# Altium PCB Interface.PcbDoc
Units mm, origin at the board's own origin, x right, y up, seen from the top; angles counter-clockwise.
Board outline 30.5 x 82 mm, 2 copper layers (Top Layer, Bottom Layer), stack 1.271 mm thick; 75 components, 43 nets, 233 pads, 361 vias.
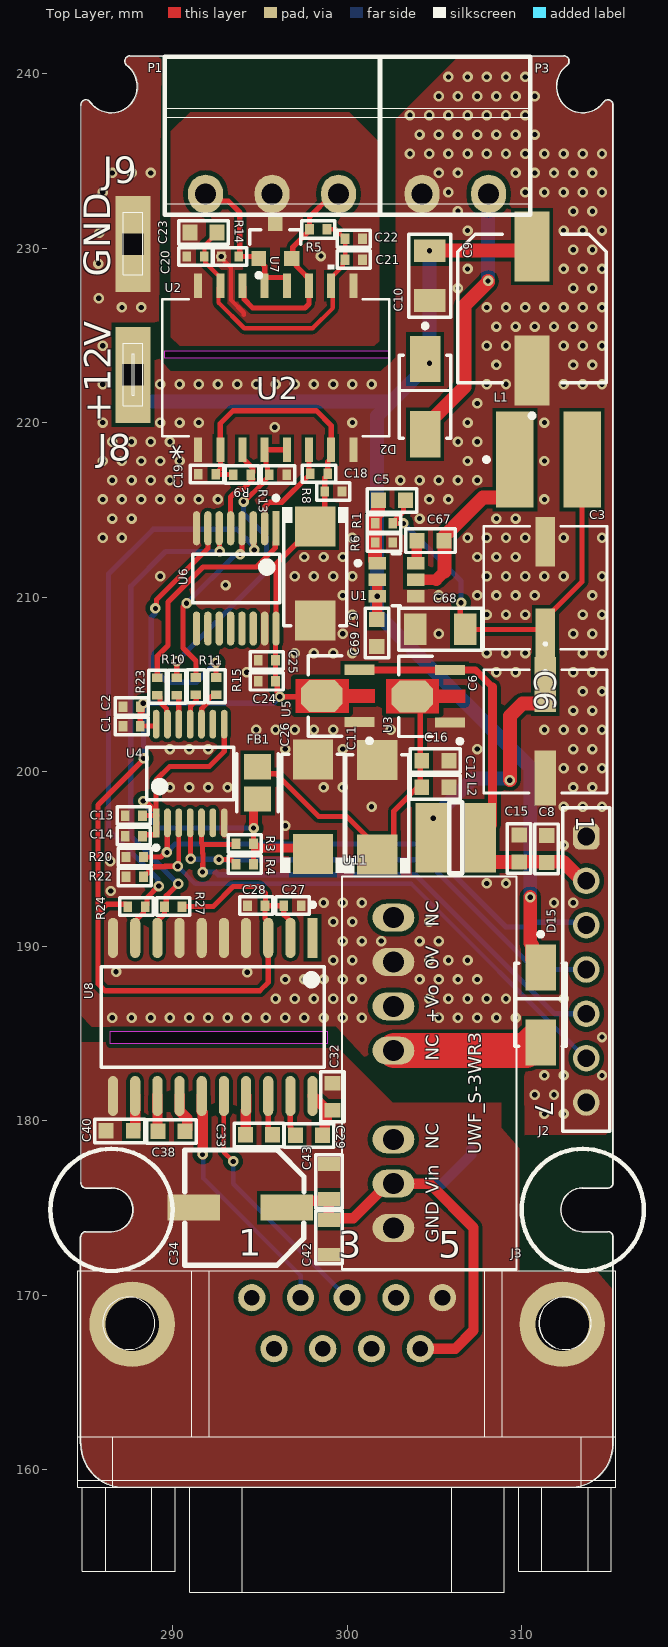
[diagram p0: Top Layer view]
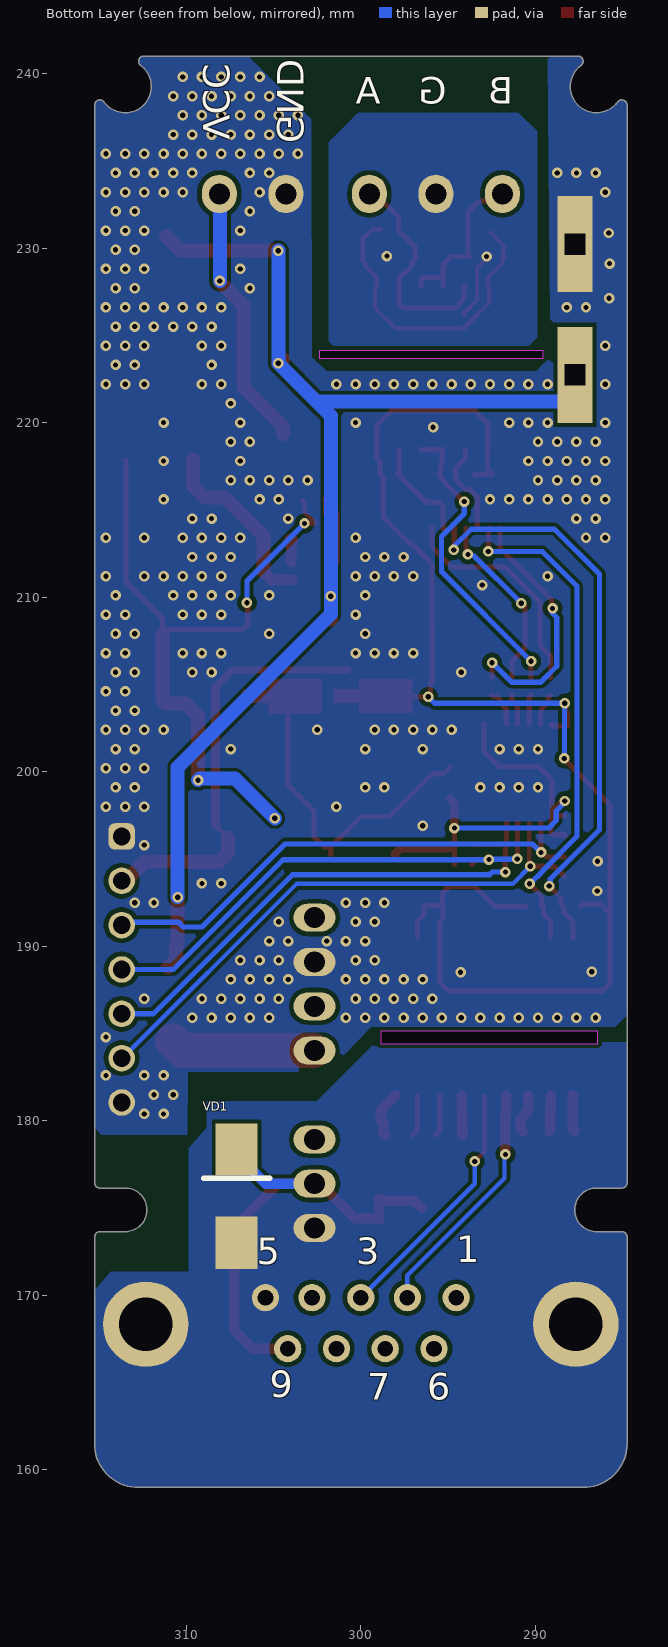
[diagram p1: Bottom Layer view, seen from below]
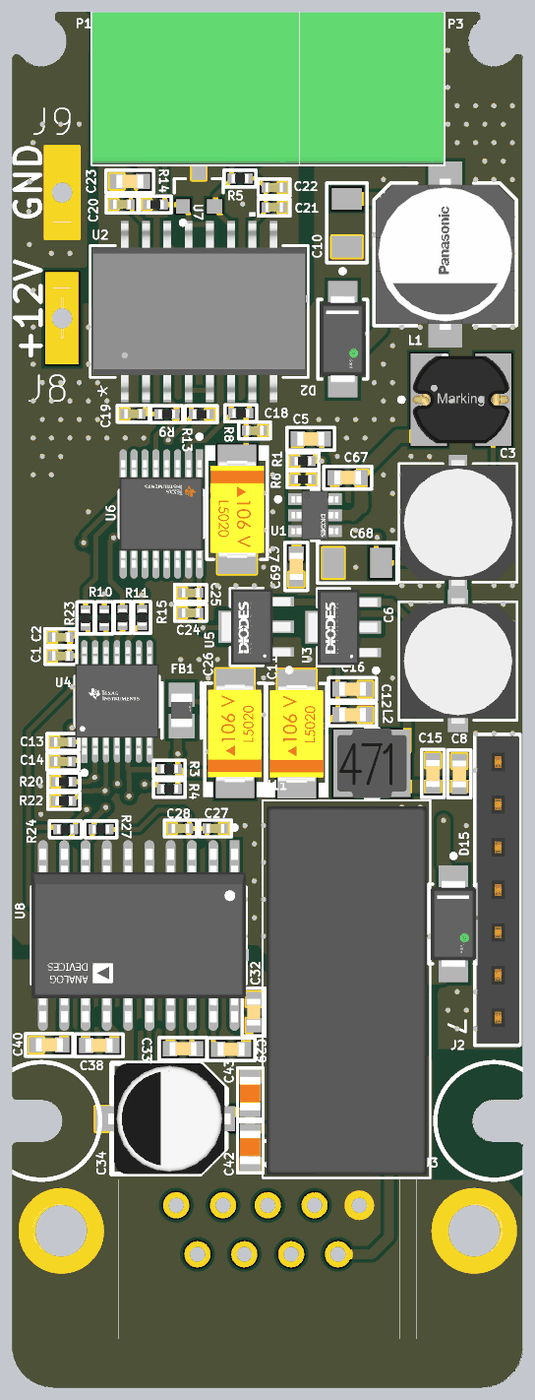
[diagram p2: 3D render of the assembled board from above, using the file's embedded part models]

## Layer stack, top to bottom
Top Solder: solder mask 0.0102, Solder Resist, Dk 3.5
Top Layer: signal copper 0.0356
Dielectric 1: dielectric 1.2, FR-4, Dk 4.8
Bottom Layer: signal copper 0.0356
Bottom Solder: solder mask 0.0102, Solder Resist, Dk 3.5

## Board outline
284.75,173.35 cw(c285.05,173.35) 285.05,173.65 286.5,173.65 ccw(c286.5,174.9) 286.5,176.15 285.05,176.15 cw(c285.05,176.45) 284.75,176.45 284.75,238.183 cw(c285.05,238.183) 285.292,238.361 ccw(c286.5,239.25) 287.389,240.458 cw(c287.567,240.7) 287.567,241 312.433,241 cw(c312.433,240.7) 312.611,240.458 ccw(c313.5,239.25) 314.708,238.361 cw(c314.95,238.183) 315.25,238.183 315.25,176.45 cw(c314.95,176.45) 314.95,176.15 313.5,176.15 ccw(c313.5,174.9) 313.5,173.65 314.95,173.65 cw(c314.95,173.35) 315.25,173.35 315.25,161.5 cw(c312.75,161.5) 312.75,159 287.25,159 cw(c287.25,161.5) 284.75,161.5
cut-out: 289.56,223.672 289.56,224.13 302.387,224.13 302.387,223.672
cut-out: 286.436,184.429 286.436,185.141 298.856,185.141 298.856,184.429
cut-out: 289.56,223.672 289.56,224.13 302.387,224.13 302.387,223.672

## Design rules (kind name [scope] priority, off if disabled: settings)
Clearance Clearance_1 [All] p1: gap=0.254 ignorepadtopadclearanceinfootprint=FALSE except(0.2: Arc-Fill Arc-Poly Arc-Region Track-Fill Track-Poly Track-Region SMDPad-SMDPad SMDPad-THPad SMDPad-Fill SMDPad-Poly SMDPad-Region)
Clearance [All] p2: gap=0.254 ignorepadtopadclearanceinfootprint=TRUE except(0.15: Via-Fill Via-Poly Via-Region; 0.2: Arc-Fill Arc-Poly Arc-Region Track-Fill Track-Poly Track-Region SMDPad-SMDPad SMDPad-Fill SMDPad-Poly SMDPad-Region)
ComponentClearance [All] p1: gap=-10 collisioncheckmode=3 verticalgap=0.1 showdistances=FALSE
HoleSize [All] p1: absolutevalues=TRUE maxlimit=4 minlimit=0.025 maxpercent=80.000 minpercent=20.000
PlaneClearance [All] p1: clearance=0.2
PlaneConnect [All] p1: planeconnectstyle=Direct reliefexpansion=0.508 reliefentries=4 reliefconductorwidth=0.254 reliefairgap=0.254
PolygonConnect [All] p1: connectstyle=Direct reliefconductorwidth=0.254 reliefentries=4 polygonreliefangle="90 Angle" airgapwidth=0.254
RoutingVias [All] p1: holewidth=0.3 width=0.6 viastyle="Through Hole" minholewidth=0.3 minwidth=0.6 maxholewidth=0.711 maxwidth=1.27
SilkToSilkClearance [All] p1: silktosilkclearance=0.1
SilkToSolderMaskClearance [IsPad] p1: minsilkscreentomaskgap=0.05 clearancetoexposedcopper=TRUE
SolderMaskExpansion SolderMaskExpansion_1 [All] p1: expansion=0.102 istentingtop=FALSE
SolderMaskExpansion Tented_Vias [IsVia] p2: expansion=0.102 istentingtop=TRUE
SupplyNets "Schematic Supply Nets_10" [InNet('VCC_2')] p1: voltage=0.000
SupplyNets "Schematic Supply Nets_8" [InNet('GND_ISOL')] p2: voltage=0.000
SupplyNets "Schematic Supply Nets_5" [InNet('3v3')] p3: voltage=0.000
SupplyNets "Schematic Supply Nets_4" [InNet('VCC')] p4: voltage=0.000
SupplyNets "Schematic Supply Nets_2" [InNet('+5V')] p5: voltage=0.000
SupplyNets "Schematic Supply Nets_1" [InNet('GND')] p6: voltage=0.000
SupplyNets "Schematic Supply Nets" [InNet('GND_2')] p7: voltage=0.000
Width [All] p1: maxlimit=3 minlimit=0.254 preferedwidth=0.254 minimp=50.000000 maximp=50.000000 favimp=50.000000
24 further rules are at their usual default settings.

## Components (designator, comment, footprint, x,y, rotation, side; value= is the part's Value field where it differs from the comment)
C1 "0.1uF 16V" CAP-0402 287.655,202.616 r180 top locked
C2 "2.2uF 16V" CAP-0402 287.655,203.733 r180 top locked
C3 "100uF 16V" CAP_A765EB_KEM-L 311.353,210.541 r90 top locked
C5 "100pF" CAP-0603 302.565,215.544 r180 top locked
C6 "100uF 16V" CAP_A765EB_KEM 311.353,202.311 r270 top locked
C7 "100uF_16V" CAP-TAN-C 298.171,211.353 r270 top locked
C8 "0.1uF" CAP-0603 311.429,195.58 r270 top locked
C9 "330uF 25V" CAP_SMD_Size_G 310.591,226.543 r90 top locked
C10 "10uF 50V" CAP-1206 304.724,228.422 r270 top locked
C11 "47uF_16V" CAP-TAN-C 301.727,197.968 r90 top locked
C12 "0.1uF" CAP-0603 305.054,199.111 r180 top locked
C13 "0.1uF 16V" CAP-0402 287.782,197.485 r180 top locked
C14 "2.2uF 16V" CAP-0402 287.782,196.317 r180 top locked
C15 "0.1uF" CAP-0603 309.855,195.605 r270 top locked
C16 "0.1uF" CAP-0603 305.054,200.635 r180 top locked
C18 "2.2uF 16V" CAP-0402 299.212,216.052 r0 top locked
C19 "0.1uF 16V" CAP-0402 291.973,217.043 r180 top locked
C20 "10nF" CAP-0402 291.313,229.514 r180 top locked
C21 "100nF" CAP-0402 300.38,229.337 r0 top locked
C22 "1nF" CAP-0402 300.38,230.53 r0 top locked
C23 "1uF" CAP-0603 291.77,230.886 r180 top locked
C24 "2.2uF 16V" CAP-0402 295.402,205.181 r180 top locked
C25 "0.1uF 16V" CAP-0402 295.402,206.375 r180 top locked
C26 "100uF_16V" CAP-TAN-C 298.044,197.993 r90 top locked
C27 "2.2uF 16V" CAP-0402 296.875,192.329 r0 top locked
C28 "0.1uF 16V" CAP-0402 294.792,192.329 r180 top locked
C29 "0.1uF 16V" CAP-0603 297.815,179.172 r0 top locked
C32 "0.1uF 16V" CAP-0603 299.161,181.381 r270 top locked
C33 "0.1uF 16V" CAP-0603 294.945,179.197 r0 top locked
C34 "100uF 50V" CAP_SMD_SIZE_D 294.132,175.031 r0 top locked
C38 "0.1uF 16V" CAP-0603 289.941,179.4 r0 top locked
C40 "0.1uF 16V" CAP-0603 286.969,179.426 r0 top locked
C42 "1 uF 25V" CAP-0805 298.958,173.33 r270 top locked
C43 "100 nF 25V" CAP-0805 298.958,176.53 r90 top locked
C67 "100nF" CAP-0603 304.775,213.233 r0 top locked
C68 "22uF 16V" CAP-1206 305.336,208.153 r180 top locked
C69 "100 nF 50V" CAP-0603 301.701,207.95 r270 top locked
D2 "SS14" DO-214-AC 304.47,221.488 r90 top locked
D15 "SS14" DO-214-AC 311.08,186.639 r90 top locked
FB1 "BLM21PG221SN1D" FP-BLM21-0_2-t0_85-e0_5-IPC_A 294.869,199.365 r90 top locked
J2 "61300711821" 61300711821 313.7,188.671 r270 top locked
J3 "'DB9公头" DB9-1 300,165.3 r0 top locked
J8 "1.2x3.7mm" Pad_conn_1.2x3.7mm#1 287.757,222.733 r90 top locked
J9 "1.2x3.7mm" Pad_conn_1.2x3.7mm#2 287.731,230.226 r90 top locked
L1 "12µH, 2A" WE-PD2_5848 311.531,217.881 r0 top locked
L2 "220uH" Coil_4.5x4.5_mm 306.222,196.215 r0 top locked
P1 "15EDGRS_3.81-3" 15EDGRC-3.81-3 295.7,233.1 r90 top locked
P3 "15EDGRC3_5-2" 16EDGRC_3.81-2 306.2,233.1 r90 top locked
R1 "270K" RES-0402 302.108,214.224 r180 top locked
R3 "10K" RES-0402 294.132,195.885 r180 top locked
R4 "10K" RES-0402 294.132,194.691 r180 top locked
R5 "10K" RES-0402 298.348,231.064 r0 top locked
R6 "30.1 K" RES-0402 302.108,213.131 r180 top locked
R8 "10K" RES-0402 298.391,217.068 r0 top locked
R9 "10K" RES-0402 293.98,217.018 r180 top locked
R10 "33R" RES-0402 290.246,204.876 r270 top locked
R11 "33R" RES-0402 291.338,204.902 r270 top locked
R13 "10K" RES-0402 296.037,217.018 r180 top locked
R14 "10K" RES-0402 293.294,229.514 r0 top locked
R15 "33R" RES-0402 292.506,204.902 r270 top locked
R20 "10K" RES-0402 287.832,195.115 r0 top locked
R22 "10K" RES-0402 287.832,193.972 r0 top locked
R23 "33R" RES-0402 289.128,204.876 r270 top locked
R24 "10K" RES-0402 287.934,192.278 r180 top locked
R27 "10K" RES-0402 290.043,192.278 r0 top locked
U1 "AP63200WU-7" FP-TSOT26-MFG 302.819,210.998 r0 top locked
U2 "ADM2687E" RI_16_2_ADI-L 295.91,223.139 r90 top locked
U3 "AMS1117-3.3" SOT-89 304.114,204.318 r90 top locked
U4 "TXU0304QPWRQ1" FP-PW0014A-IPC_B 291.008,199.898 r90 top locked
U5 "AMS1117" SOT-89 298.933,204.343 r90 top locked
U6 "TMUX1574PWR" TSSOP-16-A 293.649,211.074 r270 top locked
U7 "PSM712-LF-T7" PRKT-SOT23-3_V 295.885,230.403 r90 top locked
U8 "ADM3251EARWZ-REEL" FP-RW-20-IPC_B 292.303,185.953 r270 top locked
U11 "UWF1212S-3WR3" UWF_S-3WR3 302.65,182.753 r90 top locked
VD1 "SMBJ15A" DO-214AA 307.111,177.978 r270 bottom locked

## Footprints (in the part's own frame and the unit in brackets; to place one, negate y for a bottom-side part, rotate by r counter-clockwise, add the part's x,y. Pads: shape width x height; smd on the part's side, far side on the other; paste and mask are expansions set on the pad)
15EDGRC-3.81-3 [mm] "15EDGRC-3.81-3"
  oval 2.2x2 hole 1.2: 1(0,3.81) 2(0,0) 3(0,-3.81)
  silkscreen extent -1.19,-6.17 7.85,6.15, body extent -1.2,-6.15 7.87,6.15, height 7.2
16EDGRC_3.81-2 [mm] "16EDGRC_3.81-2"
  oval 2.2x2 hole 1.2: 1(0,1.905) 2(0,-1.905)
  silkscreen extent -1.19,-4.29 7.85,4.29, body extent -1.2,-4.3 7.87,4.3, height 7.2
61300711821 [mm] "Socket Header, Pitch 2.54 mm, THT, Vertical, single row, 7p"
  rrect50% 1.52x1.52 hole 1.02: 1(-7.62,0)
  round 1.52 hole 1.02: 2(-5.08,0) 3(-2.54,0) 4(0,0) 5(2.54,0) 6(5.08,0) 7(7.62,0)
  silkscreen extent -9.27,-1.35 9.27,1.35, body extent -9.14,-1.2 9.14,1.3, height 8.55
CAP-0402 [mm]
  rect 0.5x0.6 smd: 1(-0.5,0) 2(0.5,0)
  silkscreen extent -0.95,-0.5 0.95,0.5, body extent -0.52,-0.27 0.53,0.28, height 0.55
CAP-0603 [mm]
  rect 0.85x0.9 smd: 1(-0.775,0) 2(0.775,0)
  silkscreen extent -1.43,-0.67 1.43,0.67, body extent -0.8,-0.4 0.8,0.4, height 0.8
CAP-0805 [mm]
  rect 0.8x1.25 smd mask+0.015: 1(-1,0) 2(1,0)
  silkscreen extent -1.52,-0.76 1.52,0.76, body extent -1,-0.62 1,0.63, height 0.8
CAP-1206 [mm]
  rect 1.3x1.8 smd: 1(-1.425,0) 2(1.425,0)
  silkscreen extent -2.37,-1.2 2.37,1.2, body extent -1.68,-0.87 1.67,0.87, height 0.95
CAP-TAN-C [mm]
  rect 2.3x2.3 smd: 1(-2.7,0) 2(2.7,0)
  silkscreen extent -3.8,-1.9 3,1.9, body extent -2.9,-1.6 2.9,1.6, height 2.6
CAP_A765EB_KEM [mm]
  rect 3.143x1.213 smd paste+0 mask+0: 1(-2.675,0) 2(2.675,0)
  silkscreen extent -5.08,-3.53 3.53,3.53, body extent -3.75,-3.4 3.75,3.4, height 6.05
CAP_A765EB_KEM-L [mm]
  rect 2.843x1.113 smd paste+0 mask+0: 1(-2.625,0) 2(2.625,0)
  silkscreen extent -4.88,-3.53 3.53,3.53, body extent -3.75,-3.4 3.75,3.4, height 6.05
CAP_SMD_SIZE_D [mm] "CAP_SMD_SIZE_D"
  rect 3x1.5 smd: 1(2.413,0) 2(-2.921,0)
  silkscreen extent -3.43,-3.3 3.4,3.3, body extent -3.65,-3.3 3.65,3.3, height 7.7
CAP_SMD_Size_G [mm]
  rect 4x2 smd paste+0 mask+0: 1(3.55,0) 2(-3.55,0)
  silkscreen extent -6.27,-4.25 4.25,4.25, body extent -5.8,-4.5 5.8,4.5, height 0.25
Coil_4.5x4.5_mm [mm]
  rect 1.8x4 smd: 1(-1.397,0) 2(1.397,0)
  silkscreen extent -0.38,-2.03 0.38,2.03, body extent -2.07,-2.07 2.07,2.07, height 2.8
DB9-1 [mm] "DB9-1  PCB"
  round 1.56 hole 0.9: 1(-5.461,4.572) 2(-2.667,4.572) 3(0,4.572) 4(2.794,4.572) 5(5.461,4.572) 6(-4.191,1.651) 7(-1.397,1.651) 8(1.397,1.651) 9(4.191,1.651)
  round 4.9 hole 3.07: MH1(-12.319,3.048) MH2(12.319,3.048)
  body extent -15.41,-12.4 15.41,6, height 12.5
DO-214-AC [mm]
  rect 2.65x1.75 smd paste+0 mask+0: 1(-2.15,0) 2(2.15,0)
  silkscreen extent -2.37,-1.48 4.17,1.48, body extent -2.6,-1.36 2.6,1.36, height 2.5
DO-214AA [mm]
  rect 3x2.4 smd: 1(-0.381,0) 2(4.953,0)
  silkscreen extent 1.27,-1.91 1.27,1.9, body extent -0.53,-1.85 5.07,2.1, height 2.65
FP-BLM21-0_2-t0_85-e0_5-IPC_A [mm]
  rect 1.455x1.556 smd paste+0 mask+0: 1(-0.926,0) 2(0.926,0)
  silkscreen extent -1.65,-1.18 1.65,1.18, body extent -1,-0.63 1,0.63, height 1.05
FP-PW0014A-IPC_B [mm]
  rect 1.655x0.381 smd paste+0 mask+0: 1(-2.825,1.95)
  rrect100% 1.655x0.381 smd paste+0 mask+0: 2(-2.825,1.3) 3(-2.825,0.65) 4(-2.825,0) 5(-2.825,-0.65) 6(-2.825,-1.3) 7(-2.825,-1.95) 8(2.825,-1.95) 9(2.825,-1.3) 10(2.825,-0.65) 11(2.825,0) 12(2.825,0.65) 13(2.825,1.3) 14(2.825,1.95)
  silkscreen extent -4.37,-2.5 1.5,2.5, body extent -3.9,-2.75 3.9,2.75, height 0.25
FP-RW-20-IPC_B [mm]
  rect 2.298x0.582 smd paste+0 mask+0: 1(-4.528,5.715)
  rrect100% 2.298x0.582 smd paste+0 mask+0: 2(-4.528,4.445) 3(-4.528,3.175) 4(-4.528,1.905) 5(-4.528,0.635) 6(-4.528,-0.635) 7(-4.528,-1.905) 8(-4.528,-3.175) 9(-4.528,-4.445) 10(-4.528,-5.715) 11(4.528,-5.715) 12(4.528,-4.445) 13(4.528,-3.175) 14(4.528,-1.905) 15(4.528,-0.635) 16(4.528,0.635) 17(4.528,1.905) 18(4.528,3.175) 19(4.528,4.445) 20(4.528,5.715)
  silkscreen extent -6.55,-6.4 2.88,6.4, body extent -5.93,-6.65 5.93,6.65, height 0.25
FP-TSOT26-MFG [mm]
  rect 1x0.7 smd paste+0 mask+0: 1(-1.099,0.95) 2(-1.099,0) 3(-1.099,-0.95) 4(1.099,-0.95) 5(1.099,0) 6(1.099,0.95)
  silkscreen extent -2.32,-1.5 0.22,1.5, body extent -1.4,-1.45 1.4,1.45, height 1
Pad_conn_1.2x3.7mm#1 [mm]
  rect 5.5x2 hole 1.2 square: 1(0,0.026)
Pad_conn_1.2x3.7mm#2 [mm]
  rect 5.5x2 hole 1.2 square: 1(0,0)
PRKT-SOT23-3_V [mm] "SOT23, 3-Leads, Body 2.92x1.3mm, Pitch 0.94mm"
  rect 0.84x0.84 smd: 1(-1,0.94) 3(1,0)
  rect 0.84x0.9 smd: 2(-1,-0.94)
  silkscreen extent -2.09,-1.46 0.65,1.46, body extent -0.65,-1.46 0.65,1.46, height 1.17
RES-0402 [mm]
  rect 0.5x0.6 smd: 1(-0.5,0) 2(0.5,0)
  silkscreen extent -0.95,-0.5 0.95,0.5, body extent -0.5,-0.25 0.5,0.25, height 0.35
RI_16_2_ADI-L [mm]
  rect 1.41x0.46 smd paste+0 mask+0: 1(-4.7,4.445) 2(-4.7,3.175) 3(-4.7,1.905) 4(-4.7,0.635) 5(-4.7,-0.635) 6(-4.7,-1.905) 7(-4.7,-3.175) 8(-4.7,-4.445) 9(4.7,-4.445) 10(4.7,-3.175) 11(4.7,-1.905) 12(4.7,-0.635) 13(4.7,0.635) 14(4.7,1.905) 15(4.7,3.175) 16(4.7,4.445)
  silkscreen extent -3.93,-6.5 5.91,6.5, body extent -5.26,-6.38 5.26,6.38, height 2.64
SOT-89 [mm]
  rect 0.58x1.73 smd paste+0 mask+0: 1(-1.5,-1.781) 3(1.5,-1.781)
  oct 1.827x2.394 smd paste+0 mask+0: 2(0,0.381)
  Top Layer region: -0.38,-2.646 -0.38,-1.146 -0.967,-1.146 -0.967,1.884 0.967,1.884 0.967,-1.146 0.38,-1.146 0.38,-2.646
  silkscreen extent -2.7,-2.47 2.3,1.15, body extent -2.25,-2.42 2.25,1.68, height 1.6
TSSOP-16-A [mm] "TSSOP-16 pacadge"
  rect 1.955x0.421 smd paste+0 mask+0: 1(-2.875,2.275)
  rrect100% 1.955x0.421 smd paste+0 mask+0: 2(-2.875,1.625) 3(-2.875,0.975) 4(-2.875,0.325) 5(-2.875,-0.325) 6(-2.875,-0.975) 7(-2.875,-1.625) 8(-2.875,-2.275) 9(2.875,-2.275) 10(2.875,-1.625) 11(2.875,-0.975) 12(2.875,-0.325) 13(2.875,0.325) 14(2.875,0.975) 15(2.875,1.625) 16(2.875,2.275)
  silkscreen extent -4.73,-2.5 1.4,2.5, body extent -4.35,-3 4.35,3, height 0.25
UWF_S-3WR3 [mm]
  oval 1.6x2.4 hole 1.2: 1(-8.89,0) 2(-6.35,0) 3(-3.81,0) 5(1.27,0) 6(3.81,0) 7(6.35,0) 8(8.89,0)
  silkscreen extent -11.25,-7.05 11.25,2.95, body extent -11.09,-6.87 10.91,2.73, height 12
WE-PD2_5848 [mm] "SMD Power Inductor, 2-Leads, body 5.8x5.2mm"
  rect 2.15x5.5 smd: 1(-1.925,0) 2(1.925,0)
  silkscreen extent -3.67,-0.12 -3.42,0.12, body extent -2.9,-2.6 2.89,2.6, height 4.48

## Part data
C1 C13 C19 C25 C28: library part CAP-NON-POLAR, "0.1uF 16V X7R / GRM155R71C104KA88D"
C2 C14 C18 C24 C27: library part CAP-NON-POLAR, "2.2uF 16V X5R GRM155R61C225KE11D"
C3 C6: library part CAP_POL_SMD, "KEMET A765EB107M1CLAE025 /  / 100uF 16V 25mΩ 125mA@120Hz ±20% SMD,D6.3xL6mm Aluminum"
C5: library part CAP-NON-POLAR, "100pF 50V  C0G   Murata GRM1885C1H101JA01D"
C7 C9 C26: library part CAP_POL_SMD
C8 C12 C15 C16 C20 C21 C22 C23 C29 C32 C33 C38 C40: library part CAP-NON-POLAR
C10: library part CAP-NON-POLAR, "10uF 50V X7R  Yageo  CC1206KKX7R9BB106"
C11: library part CAP-POLAR
C34: library part CAP_POL_SMD, "100uF 50V  JVJ50V100M6x8"
C42: library part CAP-NON-POLAR, "1 uF 25V X7R"
C43: library part CAP-NON-POLAR, "100 nF 25V X7R"
C67: library part CAP-NON-POLAR, "100nF  50V  X7R  Murata GRM188R71H104KA93D"
C68: library part CAP-NON-POLAR, "22uF 16V   X7R   Murata GRM31CZ71C226ME15L"
C69: library part CAP-NON-POLAR, "100 nF 50V  X7R  GCM188R71H104KA57J"
FB1: "Chip Ferrite Bead, 0805, 220Ω @ 100MHz, 0.045Ω, 25%, 2A"
J2: "WR-PHD Socket Header, THT, Vertical, pitch 2.54mm, 1 Row, 7P", Contact Resistance=20mΩ, Manufacturer="Wurth Elektronik", Operating Temperature Max=125°C, Operating Temperature Min=-40°C, Rated Current=3A, Withstanding Voltage=500V, Working Voltage=250V
J3: library part DB9, "D-DMR009PM-D002  Ckmtw /  / 9P/弯插/公"
J8 J9: library part Klema_15_A
L1: library part 744774112, "WE-PD2 SMT Power Inductor, size 5848, 12µH, 2A, 0.11Ω", Case/Size Code=5848, DC Resistance=0.082Ω, DC Resistance Max=0.11Ω, Inductance=12µH, Manufacturer="Wurth Elektronik", Operating Temperature Max=125°C, Operating Temperature Min=-40°C, Rated Current=2A, Saturation Current=1.94A, Self Resonant Frequency=24MHz
L2: library part Coil
R1 R3 R4 R5 R8 R9 R10 R11 R13 R14 R15 R20 R22 R23 R24 R27: library part RES-CONST
R6: library part RES-CONST, "30,1 K, 1%"
U1: "AP63200WU-7  IC REG BUCK ADJUSTABLE 2A TSOT26"
U3: library part AMS1117
U4: "Translation - Voltage Levels Automotive four chan nel unidirectional"
U7: library part CMP-2000-07553-1, "TVS Array - Asymmetrical Data Line Protector, 600 W, 7.5 V, -55 to 150 degC, 3-Pin SOT23, RoHS, Tape and Reel", Capacitance=75pF, Case\/Package=SOT-23, Clamping Voltage=17V, Current=20uA, Manufacturer="Protek Devices", Max Operating Temperature=150degC, Min Breakdown Voltage=7.5V, Min Operating Temperature=-55degC, Package Description="3-Pin Small Outline Transistor, Body 2.92 x 1.3 mm, Pitch 0.94 mm", Package Reference=SOT23-3, Power Dissipation=600W, Voltage=12V, Working Voltage=7V
U8: "DGTL ISO 2.5KV 2CH RS232 20SOIC"
U11: library part UWF_S-3WR3
VD1: library part ESD_Unidirect

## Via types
v1: diameter 0.6, hole 0.3, Top Layer to Bottom Layer, tented both sides, 361 vias

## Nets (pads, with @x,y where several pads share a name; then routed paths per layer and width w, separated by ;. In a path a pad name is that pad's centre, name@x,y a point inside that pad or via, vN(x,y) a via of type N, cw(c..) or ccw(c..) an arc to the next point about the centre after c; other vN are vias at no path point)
3v3: C13.1 C14.1 C26.1 FB1.1 R3.1 R4.1 U4.1 U4.8 | length 26.5
  Top Layer w0.3: C14.1 288.36,196.395 289.017,196.395 289.098,196.476 U4.1@289.098,197.073 ; C13.1 U4.1@289.098,197.485 ; v1(288.315,198.323) 288.373,198.266 288.502,198.266 U4.1@289.058,197.71 ; U4.1 U4.1@289.058,197.71 ; U4.8 292.958,201.162 292.1,200.304 289.839,200.304 289.058,199.523 U4.1@289.058,197.71 ; R4.1 R3.1@294.632,195.635 ; R3.1 294.632,196.766 v1(294.64,196.774)
  Top Layer w0.5: R3.1 294.882,195.635 297.701,195.635 C26.1 ; v1(294.64,196.774) 294.64,198.21 FB1.1
  Bottom Layer w0.3: v1(288.315,198.323) 288.315,198.242 288.8,197.757 288.8,197.201 289.228,196.774 v1(294.64,196.774)
+5V: C1.1 C2.1 C7.1 C18.1 C19.1 C24.1 C25.1 C27.1 C28.1 R8.2 R9.2 R24.2 R27.2 U2.2 U2.7 U4.14 U5.2 U6.16 U8.2 U8.3 | length 83.6
  Top Layer w0.3: R24.2 287.307,192.405 286.258,192.405 285.725,191.872 ; C2.1@288.258,203.828 288.258,203.469 288.155,203.366 C1.1 289.02,202.616 289.058,202.653 U4.14 ; v1(288.341,200.762) 288.341,200.708 285.725,198.092 285.725,191.872 ; R27.2 292.329,192.278 293.472,193.421 294.945,193.421 295.326,193.04 295.326,192.362 C28.1 ; R9.2 293.467,217.03 292.486,217.03 C19.1 292.473,217.093 292.739,217.359 292.739,218.435 U2.2 292.735,219.939 293.472,220.675 298.247,220.675 299.085,219.837 299.085,217.964 298.891,217.77 298.891,217.018 298.712,216.839 C18.1 ; U8.2 296.748,191.44 296.375,191.813 C27.1 C28.1 ; U5.2 298.272,204.343 298.221,204.292 v1(296.139,204.292) 296.139,204.373 296.002,204.51 296.002,205.081 C24.1 C25.1 295.902,208.176 U6.16 295.924,211.901 297.077,213.053 297.171,213.053 298.712,214.595 C18.1@298.712,215.952 ; 285.725,191.872 285.725,187.858 286.131,187.452 294.996,187.452 295.478,187.935 295.478,191.416 295.292,191.601 C28.1
  Bottom Layer w0.3: v1(288.341,200.762) 288.328,200.774 288.328,203.904 v1(288.315,203.917) 295.763,203.917 v1(296.139,204.292)
GND: C1.2 C2.2 C3.2 C6.2 C7.2 C8.1 C9.2 C10.2 C11.2 C12.1 C13.2 C14.2 C15.1 C16.1 C18.2 C19.2 C24.2 C25.2 C26.2 C27.2 C28.2 C68.2 C69.2 J2.1 J2.7 J9.1 P3.1 R6.1 R13.1 R20.1 R22.1 U1.4 U2.1 U2.8 U3.1 U4.7 U5.1 U6.8 U6.15 U8.4 U8.5 U8.6 U8.7 U8.10 U11.7
  other v1: 311.3,180.4 312.4,180.4 310.75,181.5 311.85,181.5 311.3,182.6 312.4,182.6 314.6,182.6 314.6,184.8 286.55,185.9 287.65,185.9 288.75,185.9 289.85,185.9 290.95,185.9 292.05,185.9 293.15,185.9 294.25,185.9 295.35,185.9 296.45,185.9 297.55,185.9 298.65,185.9 299.75,185.9 300.85,185.9 305.25,185.9 306.35,185.9 307.45,185.9 308.55,185.9 309.65,185.9 295.9,187 297,187 298.1,187 299.2,187 300.3,187 304.7,187 305.8,187 306.9,187 308,187 309.1,187 312.4,187 296.45,188.1 297.55,188.1 298.65,188.1 299.75,188.1 300.85,188.1 304.15,188.1 305.25,188.1 306.35,188.1 307.45,188.1 294.284,188.519 286.766,188.544 299.2,189.2 300.3,189.2 304.7,189.2 305.8,189.2 306.9,189.2 299.75,190.3 300.85,190.3 301.95,190.3 304.15,190.3 305.25,190.3 299.2,191.4 300.3,191.4 304.7,191.4 298.65,192.5 299.75,192.5 300.85,192.5 311.85,192.5 312.95,192.5 286.461,193.167 308,193.6 309.1,193.6 286.436,194.869 312.4,195.8 296.45,196.9 301.4,198 312.4,198 313.5,198 314.6,198 289.85,199.1 290.95,199.1 292.05,199.1 293.15,199.1 298.65,199.1 299.75,199.1 312.95,199.1 314.05,199.1 312.4,200.2 313.5,200.2 314.6,200.2 289.85,201.3 290.95,201.3 292.05,201.3 296.45,201.3 299.75,201.3 307.45,201.3 312.95,201.3 314.05,201.3 294.8,202.4 295.9,202.4 297,202.4 298.1,202.4 299.2,202.4 302.5,202.4 311.3,202.4 312.4,202.4 313.5,202.4 314.6,202.4 312.95,203.5 314.05,203.5 313.5,204.6 314.6,204.6 294.25,205.7 308.55,205.7 309.65,205.7 312.95,205.7 314.05,205.7 297,206.8 298.1,206.8 299.2,206.8 300.3,206.8 308,206.8 309.1,206.8 310.2,206.8 313.5,206.8 314.6,206.8 299.75,207.9 305.25,207.9 312.95,207.9 314.05,207.9 300.3,209 308,209 309.1,209 310.2,209 313.5,209 314.6,209 299.75,210.1 305.25,210.1 307.45,210.1 308.55,210.1 309.65,210.1 310.75,210.1 314.05,210.1 293.04,210.693 289.3,211.2 297,211.2 298.1,211.2 299.2,211.2 300.3,211.2 308,211.2 309.1,211.2 310.2,211.2 311.3,211.2 312.4,211.2 314.6,211.2 297.55,212.3 298.65,212.3 299.75,212.3 307.45,212.3 308.55,212.3 309.65,212.3 286,213.4 287.1,213.4 300.3,213.4 306.9,213.4 308,213.4 309.1,213.4 310.2,213.4 312.4,213.4 314.6,213.4 286.55,214.5 287.65,214.5 304.15,214.5 308.55,214.5 309.65,214.5 286,215.6 287.1,215.6 288.2,215.6 289.3,215.6 290.4,215.6 291.5,215.6 292.6,215.6 304.7,215.6 305.8,215.6 311.3,215.6 286.55,216.7 287.65,216.7 288.75,216.7 289.85,216.7 303.05,216.7 304.15,216.7 305.25,216.7 306.35,216.7 307.45,216.7 286,217.8 287.1,217.8 288.2,217.8 289.3,217.8 290.4,217.8 306.9,217.8 311.3,217.8 286.55,218.9 287.65,218.9 288.75,218.9 289.85,218.9 306.35,218.9 307.45,218.9 295.859,219.735 286,220 289.3,220 290.4,220 291.5,220 300.3,220 306.9,220 311.3,220 307.45,221.1 286,222.2 289.3,222.2 290.4,222.2 291.5,222.2 292.6,222.2 293.7,222.2 294.8,222.2 295.9,222.2 297,222.2 298.1,222.2 299.2,222.2 300.3,222.2 301.4,222.2 308,222.2 309.1,222.2 312.4,222.2 313.5,222.2 314.6,222.2 308.55,223.3 312.95,223.3 314.05,223.3 286,224.4 308,224.4 309.1,224.4 312.4,224.4 313.5,224.4 314.6,224.4 308.55,225.5 309.65,225.5 310.75,225.5 311.85,225.5 312.95,225.5 314.05,225.5 287.1,226.6 288.2,226.6 308,226.6 309.1,226.6 310.2,226.6 311.3,226.6 312.4,226.6 313.5,226.6 314.6,226.6 285.775,227.127 306.35,227.7 312.95,227.7 314.05,227.7 306.9,228.8 312.4,228.8 313.5,228.8 314.6,228.8 285.75,229.108 312.95,229.9 314.05,229.9 285.801,230.861 306.9,231 312.4,231 313.5,231 314.6,231 306.35,232.1 312.95,232.1 314.05,232.1 286,233.2 305.8,233.2 310.2,233.2 311.3,233.2 312.4,233.2 313.5,233.2 314.6,233.2 286.55,234.3 287.65,234.3 288.75,234.3 305.25,234.3 306.35,234.3 309.65,234.3 310.75,234.3 311.85,234.3 312.95,234.3 314.05,234.3 303.6,235.4 304.7,235.4 305.8,235.4 306.9,235.4 308,235.4 309.1,235.4 310.2,235.4 311.3,235.4 312.4,235.4 313.5,235.4 314.6,235.4 304.15,236.5 305.25,236.5 306.35,236.5 307.45,236.5 308.55,236.5 309.65,236.5 310.75,236.5 303.6,237.6 304.7,237.6 305.8,237.6 306.9,237.6 308,237.6 309.1,237.6 310.2,237.6 305.25,238.7 306.35,238.7 307.45,238.7 308.55,238.7 309.65,238.7 310.75,238.7 305.8,239.8 306.9,239.8 308,239.8 309.1,239.8 310.2,239.8
GND_2: C32.1 C34.2 C40.1 C42.2 C43.2 J3.5 J3.MH1 J3.MH2 U8.11 U11.1 VD1.2
GND_ISOL: C20.2 C21.2 C22.2 C23.2 P1.2 R14.1 U2.9 U2.16 U7.3 | length 3.9
  Top Layer w0.254: R14.1@292.794,229.464 v1(292.794,229.514) 292.917,229.391 292.917,229.303 293.346,228.873 293.346,227.024 294.081,226.289 294.081,226.162
  other v1: 298.501,229.54
NetC3_1: C3.1 C5.1 C6.1 C68.1 L1.2 L2.1 R1.1 | length 40.1
  Top Layer w0.3: R1.1 v1(303.225,214.224) ; R1.1@302.608,214.274 303.228,214.894 303.228,215.433 C5.1 ; v1(306.527,209.677) 306.476,209.626 306.476,208.438 C68.1 311.158,208.153 311.353,208.348 311.353,208.781 313.456,210.884 L1.2
  Top Layer w0.8: v1(309.321,199.517) 309.321,203.2 310.036,203.914 311.197,203.914 311.353,204.071 311.353,204.936 C3.1
  Bottom Layer w0.3: v1(303.225,214.224) 306.527,210.922 v1(306.527,209.677)
  Bottom Layer w0.8: v1(304.927,197.333) 307.213,199.619 309.22,199.619 v1(309.321,199.517)
NetC5_2: C5.2 R1.2 R6.2 U1.1 | length 3.7
  Top Layer w0.8: U1.1@301.719,212.002 301.608,212.114 R6.2 301.608,214.698 301.765,214.856 301.765,215.519 C5.2
NetC11_1: C11.1 C12.2 C16.2 FB1.2 U3.2 | length 19.3
  Top Layer w0.3: FB1.2 295.272,199.887 295.921,199.887 298.374,197.434 299.974,197.434 C11.1@301.727,195.682 ; C11.1 301.727,195.707 302.114,195.707 302.675,196.268 302.675,197.748 304.19,199.263 304.19,200.635 304.19,203.86 U3.2
NetC20_1: C20.1 C21.1 C22.1 C23.1 R5.2 U2.10 U2.15 | length 18
  Top Layer w0.254: C20.1@291.762,229.464 291.885,229.341 291.885,229.164 292.735,228.314 U2.15 292.632,227.736 292.632,226.874 294.107,225.4 298.018,225.4 299.187,226.568 299.187,227.737 U2.10 299.085,228.314 299.757,228.986 299.757,229.164 299.88,229.287 299.88,230.58 299.757,230.703 299.707,230.703 299.347,231.064 R5.2 ; C20.1 291.828,229.53 291.828,230.145 292.545,230.861 C23.1
NetC29_1: C29.1 U8.19 | length 2.4
  Top Layer w0.3: U8.19 296.748,179.647 296.765,179.631 296.765,179.447 C29.1
NetC29_2: C29.2 C32.2 U8.20 | length 2.7
  Top Layer w0.6: U8.20 298.846,180.598 298.846,180.101 298.715,179.97 298.715,179.297 C29.2
NetC33_1: C33.1 U8.17 | length 2.2
  Top Layer w0.6: C33.1 294.199,179.226 294.199,180.576 294.208,180.585 U8.17
NetC33_2: C33.2 U8.18 | length 2.3
  Top Layer w0.3: U8.18 295.478,179.439 C33.2
NetC34_1: C34.1 C42.1 C43.1 J3.9 U11.2 VD1.1 | length 28.8
  Top Layer w0.6: C34.1 296.944,175.43 298.858,175.43 C43.1 ; C42.1 299.058,174.43 300.344,174.43 302.317,176.403 302.717,176.403 304.724,176.403 307.238,173.888 307.238,167.996 306.194,166.951 J3.9 ; C42.1 C43.1
  Bottom Layer w0.6: U11.2@302.717,176.403 305.456,176.403 307.111,178.059 VD1.1
NetC38_1: C38.1 U8.13 | length 2
  Top Layer w0.6: U8.13 289.128,180.585 289.137,180.576 289.137,179.429 C38.1
NetC38_2: C38.2 U8.14 | length 2.3
  Top Layer w0.6: U8.14 290.398,180.585 290.845,180.139 290.845,179.819 290.841,179.815 290.841,179.525 C38.2
NetC40_2: C40.2 U8.12 | length 2
  Top Layer w0.6: C40.2 287.849,179.531 287.849,181.416 U8.12
NetC67_1: C67.1 U1.6 | length 1.2
  Top Layer w0.6: U1.6@303.997,212.002 C67.1@303.997,213.231
  Top Layer w0.8: C67.1@303.997,213.231 C67.1
NetC67_2: C67.2 L1.1 U1.5 | length 10.6
  Top Layer w0.6: U1.5 305.105,210.998
  Top Layer w0.7: 305.105,210.998 305.587,211.48
  Top Layer w0.8: 305.587,211.48 305.587,212.143 305.575,212.156 305.575,213.208 305.547,213.235 305.575,213.263 305.575,213.5 307.772,215.697 308.931,215.697 309.606,216.372 L1.1
NetD2_1: D2.1 P3.2 | length 15.3
  Top Layer w0.8: D2.1 304.47,219.788 306.73,222.049 306.73,226.72 308.077,228.067 v1(308.077,228.117)
  Bottom Layer w0.8: v1(308.077,228.117) 308.077,233.072 P3.2
NetD15_1: D15.1 U11.5 | length 8.3
  Top Layer w2: U11.5@302.717,184.023 310.236,184.023 D15.1@310.794,184.582
NetJ2_3: J2.3 R20.2 U4.2 | length 29.5
  Top Layer w0.3: R20.2 289.334,195.115 289.596,195.377 v1(289.677,195.377) ; v1@289.692,195.361 289.692,197.057 U4.2
  Bottom Layer w0.3: v1(289.677,195.377) 290.158,195.858 304.344,195.858 309.093,191.11 310.18,191.11 310.452,191.382 313.494,191.382 J2.3@313.665,191.211
NetJ2_4: J2.4 R4.2 U4.4 | length 28.4
  Top Layer w0.3: U4.4 291.023,197.057 291.023,195.02 v1(291.039,195.004) ; v1(292.659,194.97) 293.353,194.97 293.482,194.841 293.532,194.841 293.632,194.741 R4.2
  Bottom Layer w0.3: v1(291.039,195.004) 291.056,194.987 292.63,194.987 292.659,194.958 304.46,194.958 310.748,188.671 J2.4@313.665,188.671
NetJ2_5: J2.5 R3.2 U4.5 | length 30.1
  Top Layer w0.3: U4.5 291.658,195.895 291.719,195.834 ; v1@291.712,194.261 291.732,194.281 291.732,194.702 291.743,194.713 291.743,195.296 291.712,195.327 291.712,195.834 293.581,195.834 R3.2
  Bottom Layer w0.3: v1(291.719,194.254) 292.469,194.254 292.619,194.104 303.902,194.104 311.876,186.131 J2.5@313.665,186.131
NetJ2_6: J2.6 R22.2 U4.3 | length 32.7
  Top Layer w0.254: v1(290.298,194.579) 290.358,194.638 U4.3
  Top Layer w0.3: R22.2 288.332,194.022 288.432,194.122 288.482,194.122 288.921,194.561 289.563,194.561 289.581,194.579 v1(290.298,194.579)
  Bottom Layer w0.254: v1(290.298,194.579) 291.304,193.573 303.682,193.573 J2.6@313.665,183.591
NetJ3_2: J3.2 U8.15 | length 13.9
  Top Layer w0.6: U8.15 291.668,180.523 291.719,180.472 v1(291.719,178.079)
  Bottom Layer w0.254: v1(291.719,178.079) 291.77,178.029 291.77,176.708 297.333,171.145 J3.2
NetJ3_3: J3.3 U8.16 | length 14.5
  Top Layer w0.254: U8.16 292.938,178.206 v1(293.472,177.673)
  Bottom Layer w0.254: v1(293.472,177.673) 293.472,176.4 J3.3
NetP1_1: P1.1 R14.2 U2.12 U2.13 U7.1 | length 10.4
  Top Layer w0.3: P1.1@291.694,232.994 291.999,232.689 293.193,232.689 293.855,232.027 293.855,229.525 R14.2@293.819,229.489 ; R14.2 294.834,229.514 U7.1 ; U7.1@294.97,229.378 295.215,229.133 295.215,229.018 295.275,228.958 295.275,228.417 U2.13 ; U2.13@295.275,228.314 296.465,228.314 296.545,228.234 U2.12
  Bottom Layer w0.254: P1.1@291.694,232.994 P1.1@291.694,233.69
NetP1_3: P1.3 R5.1 U2.11 U2.14 U7.2 | length 13.4
  Top Layer w0.3: U2.14 294.085,227.759 294.085,227.072 294.589,226.568 297.586,226.568 297.815,226.797 297.815,228.314 297.712,228.417 297.633,228.417 297.097,228.953 297.097,228.983 297.071,229.009 297.071,229.157 U7.2 296.89,229.469 296.89,230.056 297.848,231.014 297.848,231.778 299.065,232.994 P1.3@299.314,232.994
  Bottom Layer w0.254: P1.3@299.314,232.994 P1.3@299.314,233.74
NetR8_1: R8.1 U2.6 U6.2 | length 6.1
  Top Layer w0.3: U6.2 295.274,215.166 295.551,215.443 296.266,215.443 297.741,216.918 297.791,216.918 297.891,217.018 R8.1 297.815,217.145 U2.6
NetR9_1: R9.1 U2.3 U6.5 | length 5.5
  Top Layer w0.3: U6.5 293.324,215.727 293.776,216.179 294.03,216.179 294.608,216.757 294.58,216.786 R9.1@294.58,217.018 ; U2.3 294.005,217.964 294.608,217.361 294.608,217.168 294.608,217.146 R9.1
NetR10_1: R10.1 R13.2 U2.4 U2.5 | length 17.7
  Top Layer w0.3: R10.1 v1(290.246,206.324) ; v1(294.068,215.475) 294.11,215.475 295.162,216.528 295.162,216.57 295.437,216.844 295.437,216.918 R13.2 295.437,217.118 295.437,217.498 295.355,217.58 295.355,218.359 U2.4 U2.5
  Bottom Layer w0.3: v1(290.246,206.324) 295.382,211.461 295.382,213.476 294.068,214.79 v1(294.068,215.475)
NetR10_2: R10.2 U4.12 | length 1.7
  Top Layer w0.3: R10.2 290.258,204.376 290.358,204.276 U4.12
NetR11_1: R11.1 U6.4 | length 10.4
  Top Layer w0.3: v1(290.805,209.652) 290.601,209.448 290.601,207.086 291.338,206.35 R11.1 ; v1(293.864,212.447) 293.864,212.528 293.974,212.638 U6.4
  Bottom Layer w0.3: v1(290.805,209.652) 293.542,212.389 293.807,212.389 v1(293.864,212.447)
NetR11_2: R11.2 U4.11 | length 1.8
  Top Layer w0.3: U4.11 291.023,202.739 291.023,203.749 291.363,204.089 291.363,204.376 R11.2
NetR15_1: R15.1 U6.7 | length 14.7
  Top Layer w0.3: v1(289.016,209.357) 289.074,209.414 289.074,209.847 292.024,212.798 U6.7 ; v1(292.481,206.248) 292.481,205.427 R15.1
  Bottom Layer w0.3: v1(289.016,209.357) 289.029,209.344 289.029,209.096 288.773,208.839 288.773,206.045 289.687,205.13 291.363,205.13 v1(292.481,206.248)
NetR15_2: R15.2 U4.10 | length 2.1
  Top Layer w0.3: U4.10 291.673,202.739 291.673,203.615 292.042,203.984 292.042,204.126 292.218,204.302 292.406,204.302 R15.2
NetR23_1: R23.1 U6.1 | length 13.2
  Top Layer w0.3: R23.1 289.128,206.629 289.738,207.239 289.738,209.728 291.744,211.734 294.792,211.734 295.889,212.831 295.889,213.122 295.924,213.157 U6.1
NetR23_2: R23.2 U4.13 | length 1.9
  Top Layer w0.3: R23.2 289.178,204.376 289.278,204.276 289.278,203.981 289.652,203.607 289.652,203.438 289.708,203.383 U4.13
NetR24_1: R24.1 U6.3 U8.9 | length 33.9
  Top Layer w0.3: U8.9 287.858,191.44 288.341,191.922 288.341,192.184 R24.1 288.534,192.378 288.534,192.781 v1(289.202,193.449) ; U6.3 294.648,213.926 294.648,212.734 v1(294.678,212.703)
  Bottom Layer w0.3: v1(289.202,193.449) 289.149,193.501 289.149,193.857 286.334,196.672 286.334,211.328 288.9,213.893 293.677,213.893 294.615,212.956 294.615,212.848 294.678,212.785 v1(294.678,212.703)
NetR27_1: R27.1 U6.6 U8.8 | length 29.1
  Top Layer w0.3: U8.8 289.128,191.44 289.535,191.846 289.535,192.27 289.643,192.378 289.643,192.894 v1(290.331,193.583) ; U6.6 292.689,213.934 292.689,212.631 v1(292.705,212.616)
  Bottom Layer w0.3: v1(290.331,193.583) 290.299,193.583 289.594,194.287 289.594,194.319 287.611,196.303 287.611,210.624 289.604,212.616 v1(292.705,212.616)
VCC: C9.1 C10.1 C69.1 D2.2 D15.2 J8.1 U1.2 U1.3 | length 71.5
  Top Layer w0.6: C69.1@301.719,208.743 v1(301.719,210.048) U1.2
  Top Layer w0.8: C69.1 C69.1@301.719,208.743 ; D2.2 304.479,223.638 v1(304.724,223.393) ; v1(304.724,229.847) 310.346,229.847 C9.1 C9.1@311.15,230.651 ; v1(310.49,192.811) 310.49,190.183 310.599,190.074 310.599,189.264 D15.2@311.074,188.789
  Bottom Layer w0.8: J8.1@287.757,222.733 287.757,221.809 288.357,221.209 302.539,221.209 ; v1(304.724,229.847) v1(304.724,223.393) 302.539,221.209 ; v1(310.49,192.811) 310.49,200.254 301.719,209.024 v1(301.719,210.048) 301.719,220.389 302.539,221.209
VCC_2: C8.2 C15.2 J2.2 L2.2 U3.3 U5.3 | length 24.6
  Top Layer w0.3: U5.3 U5.3@300.739,205.818 ; L2.2 L2.2@308.331,196.926
  Top Layer w0.4: U5.3@300.739,205.818 U3.3 307.364,205.818 308.331,204.851
  Top Layer w0.5: L2.2@308.331,196.926 308.331,204.851
  Top Layer w0.8: L2.2 307.619,195.33 308.119,194.83 C15.2 309.868,194.843 312.378,194.843 313.47,193.751 J2.2@313.665,193.751
pads on no net: J3.1 J3.4 J3.6 J3.7 J3.8 U4.6 U4.9 U6.9 U6.10 U6.11 U6.12 U6.13 U6.14 U8.1 U11.3 U11.6 U11.8

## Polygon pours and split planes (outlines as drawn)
GND on Bottom Layer "GND_L02_P014" (solid, pour order 14): 285.417,185.404 299.41,185.393 301.831,182.829 309.917,182.814 309.944,179.188 314.869,179.203 315.248,179.596 315.248,238.176 ccw(c314.948,238.176) 314.706,238.354 cw(c313.498,239.242) 312.609,240.451 ccw(c312.431,240.692) 312.431,240.992 306.33,240.992 306.328,240.872 302.832,237.385 302.814,223.747 301.955,222.937 289.924,222.96 289.126,223.814 289.283,240.992 287.564,240.992 ccw(c287.564,240.692) 287.386,240.451 cw(c286.498,239.242) 285.289,238.354 ccw(c285.048,238.176) 284.748,238.176 284.748,186.076 284.746,186.077
GND_2 on Bottom Layer "GND_2_L02_P008" (solid, pour order 8): 284.711,161.504 ccw(c287.211,161.504) 287.211,159.004 312.711,159.004 ccw(c312.711,161.504) 315.211,161.504 315.211,170.319 314.327,171.37 309.848,171.37 309.848,178.439 308.833,179.607 308.833,181.127 302.523,181.127 299.127,184.513 284.711,184.513 284.711,176.454 ccw(c285.011,176.454) 285.011,176.154 286.461,176.154 cw(c286.461,174.904) 286.461,173.654 285.011,173.654 ccw(c285.011,173.354) 284.711,173.354
GND_ISOL on Bottom Layer "GND_ISOL_L02_P004" (solid, pour order 4): 289.89,236.677 290.97,237.757 300.139,237.757 301.841,236.055 301.841,224.65 301.231,224.041 290.741,224.041 289.89,224.892
GND_2 on Top Layer "GND_2_L01_P010" (solid, pour order 10): 284.711,161.504 ccw(c287.211,161.504) 287.211,159.004 312.711,159.004 ccw(c312.711,161.504) 315.211,161.504 315.211,170.319 314.327,171.37 309.848,171.37 309.848,178.439 308.833,179.607 308.833,181.051 302.6,181.051 299.127,184.513 284.711,184.513 284.711,176.454 ccw(c285.011,176.454) 285.011,176.154 286.461,176.154 cw(c286.461,174.904) 286.461,173.654 285.011,173.654 ccw(c285.011,173.354) 284.711,173.354
GND on Top Layer "GND_L01_P012" (solid, pour order 12): 285.375,185.397 299.368,185.387 301.789,182.823 310.146,182.807 310.173,179.182 314.827,179.197 315.206,179.59 315.206,179.589 315.206,238.169 ccw(c314.906,238.169) 314.664,238.347 cw(c313.456,239.236) 312.567,240.444 ccw(c312.389,240.686) 312.389,240.986 306.288,240.986 306.286,240.866 302.79,237.378 302.772,223.74 301.914,222.931 289.893,222.953 289.186,223.71 289.343,240.986 287.522,240.986 ccw(c287.522,240.686) 287.345,240.444 cw(c286.456,239.236) 285.247,238.347 ccw(c285.006,238.169) 284.706,238.169 284.706,186.069 284.704,186.071
GND_ISOL on Top Layer "GND_ISOL_L01_P002" (solid, pour order 2): 289.908,236.694 291,237.786 300.11,237.786 301.828,236.068 301.828,224.663 301.235,224.07 290.721,224.07 289.908,224.883

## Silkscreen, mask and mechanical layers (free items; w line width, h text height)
Top Overlay:
  drawing of 190 lines, arcs and shapes, not listed
  text "GND" at 286.436,228.346 h1.52 r90
  text "+12V" at 286.461,219.989 h1.52 r90
Bottom Overlay:
  text "B" at 291.262,238.277 h1.52
  text "G" at 295.072,238.252 h1.52
  text "A" at 298.856,238.252 h1.52
  text "VCC" at 309.016,236.195 h1.52 r90
  text "GND" at 304.775,235.991 h1.52 r90
Mechanical 1:
  lines w0.013: 284.75,176.45 ccw(c285.05,176.45) 285.05,176.15 286.5,176.15 cw(c286.5,174.9) 286.5,173.65 285.05,173.65 ccw(c285.05,173.35) 284.75,173.35 284.75,161.5 ccw(c287.25,161.5) 287.25,159 312.75,159 ccw(c312.75,161.5) 315.25,161.5 315.25,173.35 ccw(c314.95,173.35) 314.95,173.65 313.5,173.65 cw(c313.5,174.9) 313.5,176.15 314.95,176.15 ccw(c314.95,176.45) 315.25,176.45 ; 284.75,238.183 cw(c285.05,238.183) 285.292,238.361 ; 287.389,240.458 cw(c287.567,240.7) 287.567,241 312.433,241 cw(c312.433,240.7) 312.611,240.458 ; 314.708,238.361 cw(c314.95,238.183) 315.25,238.183
  lines w0.1: 286.436,184.429 298.856,184.429 298.856,185.141 286.436,185.141 286.436,184.429
  lines w0.254: 289.56,223.672 302.387,223.672 302.387,224.13 289.56,224.13 289.56,223.672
